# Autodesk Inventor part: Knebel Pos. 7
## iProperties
Created: 2009-11
Part Number: Knebel Pos. 7
Document SubType Name: Modeling
Designer: user
Author: user
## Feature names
1. Extrusion1
2. Extrusion2
3. Extrusion3
4. Fase1 [Chamfer]
